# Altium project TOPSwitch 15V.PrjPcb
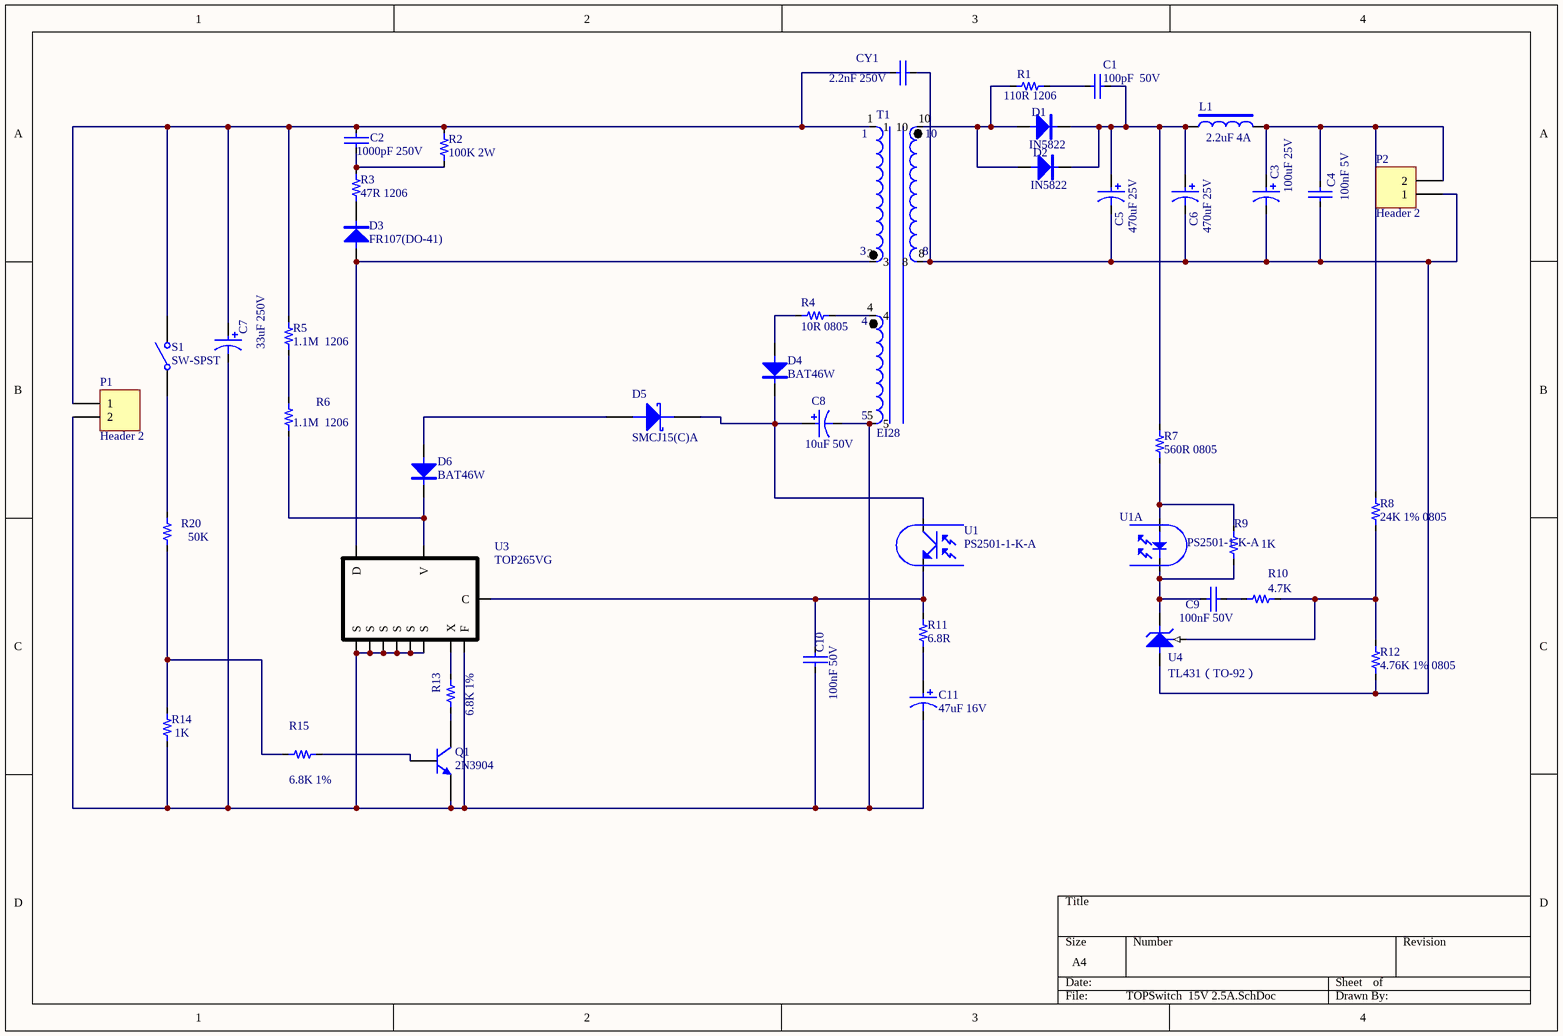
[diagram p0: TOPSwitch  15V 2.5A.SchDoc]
1 sheet, 44 parts. Net scope: global (net labels, ports and power ports of the same name join across sheets).
Board file: TOPSwitch 15V.PcbDoc

## Sheet TOPSwitch  15V 2.5A.SchDoc
size A4

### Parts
(Parts that share a designator on the sheet are numbered #1, #2 ... from top to bottom, then left to right.)
C1  100pF  50V  [0805]
C2  1000pF 250V  [1210]
C3  100uF 25V  [RB.1/.2]
C4  100nF 5V  [0603]
C5  470uF 25V  [RB.1/.2]
C6  470uF 25V  [RB.1/.2]
C7  33uF 250V  [RB.2/.5]
C8  10uF 50V  [RB.1/.2]
C9  100nF 50V  [0603]
C10  100nF 50V  [0603]
C11  47uF 16V  [RB.1/.2]
CY1  2.2nF 250V  [RAD-0.4]
D1  IN5822  [DO-201]
D2  IN5822  [DO-201]
D3  FR107(DO-41)  [DO-41]
D4  BAT46W  [DO-41]
D5  SMCJ15(C)A  [DO-213AA]
D6  BAT46W  [SOD-123]
L1  2.2uF 4A  [RL822]
P1  Header 2  [ME040-38102]
P2  Header 2  [ME040-38102]
Q1  2N3904  [SOT-23]
R1  110R 1206  [1206]
R2  100K 2W  [2512]
R3  47R 1206  [1206]
R4  10R 0805  [0805]
R5  1.1M  1206  [1206]
R6  1.1M  1206  [1206]
R7  560R 0805  [0805]
R8  24K 1% 0805  [0603]
R9  1K  [0603]
R10  4.7K  [0603]
R11  6.8R  [0805]
R12  4.76K 1% 0805  [0603]
R13  6.8K 1%  [0603]
R14  1K  [0603]
R15  6.8K 1%  [0603]
R20  50K  [0603]
S1  SW-SPST  [SPST-2]
T1  EI28  [BYQ]
U1#1  PS2501-1-K-A  [4—DIP]
U1#2  PS2501-1-K-A  [4—DIP]  (part A of 2)
U3  TOP265VG  [e-DIP12]
U4  TL431（TO-92）  [TO-92]

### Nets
NetC1_1: C1.1 R1.2
NetC1_2: C1.2 C5.1 C6.1 D1.2(K) D2.2(K) L1.1 R7.2
NetC2_1: C2.1 C7.1 CY1.1 P1.1 R2.2 R5.2 S1.2(NO) T1.1
NetC2_2: C2.2 R2.1 R3.2
NetC3_1: C3.1 C4.1 L1.2 P2.2 R8.2
NetC3_2: C3.2 C4.2 C5.2 C6.2 CY1.2 P2.1 R12.1 T1.8 U4.2(A)
NetC7_2: C7.2 C8.2 C10.2 C11.2 P1.2 Q1.1(E) R14.1 T1.5 U3.4(F) U3.7(S) U3.8(S) U3.9(S) U3.10(S) U3.11(S) U3.12(S)
NetC8_1: C8.1 D4.2(K) D5.2(k) U1#1.4(C)
NetC9_1: C9.1 R9.1 U1#2.2(K) U4.3(K)
NetC9_2: C9.2 R10.1
NetC10_1: C10.1 R11.2 U1#1.3(E) U3.3(C)
NetC11_1: C11.1 R11.1
NetD1_1: D1.1(A) D2.1(A) R1.1 T1.10
NetD3_1: D3.1(A) T1.3 U3.6(D)
NetD3_2: D3.2(K) R3.1
NetD4_1: D4.1(A) R4.2
NetD5_1: D5.1(A) D6.1(A)
NetD6_2: D6.2(K) R6.1 U3.1(V)
NetQ1_2: Q1.2(B) R15.1
NetQ1_3: Q1.3(C) R13.1
NetR4_1: R4.1 T1.4
NetR5_1: R5.1 R6.2
NetR7_1: R7.1 R9.2 U1#2.1(A)
NetR8_1: R8.1 R10.2 R12.2 U4.1(VREF)
NetR13_2: R13.2 U3.2(X)
NetR14_2: R14.2 R15.2 R20.1
NetR20_2: R20.2 S1.1(COMMON)

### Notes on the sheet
- (near T1) 1
- (near T1) 10
- (near T1) 3
- (near T1) 8
- (near T1) 4
- (near T1) 5

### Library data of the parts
C1 C2 C4 C9 C10 CY1 = CAP1
C3 C5-C8 C11 = CAP7
D1-D4 D6 = 1N4001(DO-41)
D5 = DIODE SCHOTTKY: Schottky Diode
L1 = INDUCTOR2
P1 P2 = Header 2: Header, 2-Pin
Q1 = 2N3904: NPN General Purpose Amplifier
R1-R15 R20 = RESISTOR-S
S1 = SW-SPST: Single-Pole, Single-Throw Switch
T1 = INDUCTOR ISOLATED
U1#1 = PC817-B
U1#2 = PC817-A
U4 = TL431(TO-92)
